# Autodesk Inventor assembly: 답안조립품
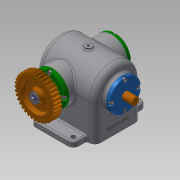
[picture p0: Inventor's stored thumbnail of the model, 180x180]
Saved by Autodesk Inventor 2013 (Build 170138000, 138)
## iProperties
Created: 2019-05
Part Number: 답안조립품
Document SubType Name: Assembly
Designer: Administrator
Mass: 2023.52 g
Surface Area: 1805.89 cm^2
Volume: 591.185 cm^3
Density: 3.42281 g/cm^3
Author: Administrator
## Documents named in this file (16)
- C:\Users\Administrator\Desktop\390504V1032\답안조립품.iam
- C:\Users\Administrator\Desktop\390504V1032\본체.ipt
- C:\Users\Administrator\Desktop\390504V1032\가변스프링.ipt
- C:\Users\Administrator\Desktop\390504V1032\가이드부시.ipt
- C:\Users\Administrator\Desktop\390504V1032\베어링 6203.ipt
- C:\Users\Administrator\Desktop\390504V1032\볼트 M4x8.ipt
- C:\Users\Administrator\Desktop\390504V1032\볼트 M4x10.ipt
- C:\Users\Administrator\Desktop\390504V1032\스퍼기어.ipt
- C:\Users\Administrator\Desktop\390504V1032\스프링와셔.ipt
- C:\Users\Administrator\Desktop\390504V1032\슬라이더.ipt
- C:\Users\Administrator\Desktop\390504V1032\오일 실 17 32 8.ipt
- C:\Users\Administrator\Desktop\390504V1032\커버 A.ipt
- C:\Users\Administrator\Desktop\390504V1032\커버 B.ipt
- C:\Users\Administrator\Desktop\390504V1032\키 4x4x14.ipt
- C:\Users\Administrator\Desktop\390504V1032\편심축.ipt
- C:\Users\Administrator\Desktop\390504V1032\평와셔.ipt
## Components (2 placed, 2 different names)
1. 가변스프링:1
2. 가이드부시:1
